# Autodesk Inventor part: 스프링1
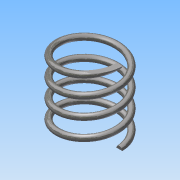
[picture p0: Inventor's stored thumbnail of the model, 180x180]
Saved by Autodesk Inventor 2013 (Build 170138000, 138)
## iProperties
Created: 2016-07
Part Number: 스프링1
Material: 스테인리스강
Document SubType Name: Modeling
Designer: Administrator
Mass: 6.2731 g
Surface Area: 15.7615 cm^2
Volume: 0.776373 cm^3
Density: 8.08 g/cm^3
Author: Administrator
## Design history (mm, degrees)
sketch "스케치1"
  geometry: L1 (0, 0)-(10, 0); L2 (10, 0)-(10, 25); L3 (10, 25)-(0, 25); L4 (0, 25)-(0, 0); C1 r 1 at (10, 25)
  constraints: 8 end point, 2 parallel, 1 centre point, 1 coincident, 1 horizontal, 1 perpendicular
  dimensions: "d0" = 20 diameter of L2 L4; "d2" = 25 distance between parallel lines of L1 L3 (derived); "d3" = 2 diameter of C1
feature "코일1" sketch "스케치1" pitch "d4" = 10; turns "d6" = 4; dims "d5" = 25 (= d2), "d7" = 0, angle "d8" = 90 deg, angle "d9" = 90 deg, "d10" = 0, "d11" = 0
feature "분할1"
node "작업 평면1"
feature "분할2"
node "솔리드1"
other parameters: "d12" = 25
